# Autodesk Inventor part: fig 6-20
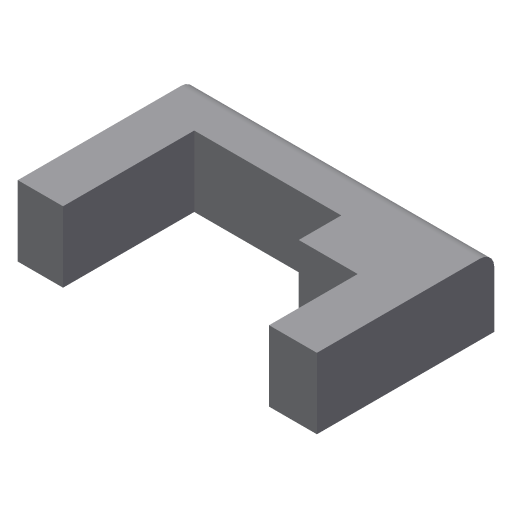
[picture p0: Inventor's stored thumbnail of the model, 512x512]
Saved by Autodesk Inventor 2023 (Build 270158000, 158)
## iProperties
Created: 2010-08
Part Number: fig 6-20
Document SubType Name: Modeling
Designer: CADSoft
Density: 1 g/cm^3
Material: Generic
Appearance: Default
Author: CADSoft
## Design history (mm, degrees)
sketch "Sketch1"
  geometry: L1 (-25.394, 25.152)-(17.03, 25.152); L2 (17.03, 25.152)-(17.03, 0); L3 (-25.394, 0)-(-25.394, 25.152); L4 (10.242, 0)-(10.242, 12.576); L5 (10.242, 12.576)-(1.879, 12.576); L6 (1.879, 12.576)-(1.879, 18.606); L7 (1.879, 18.606)-(-18.97, 18.606); L8 (-18.97, 18.606)-(-18.97, 0); L9 (17.03, 0)-(10.242, 0); L10 (-18.97, 0)-(-25.394, 0); 1 further point
  constraints: 20 end point, 6 parallel, 4 perpendicular, 1 horizontal
extrude "Extrusion1" new body sketch "Sketch1" distance "d0" = 10; taper "d1" = 0 deg
fillet "Fillet1" dims "d2" = 2
body "Solid1"
